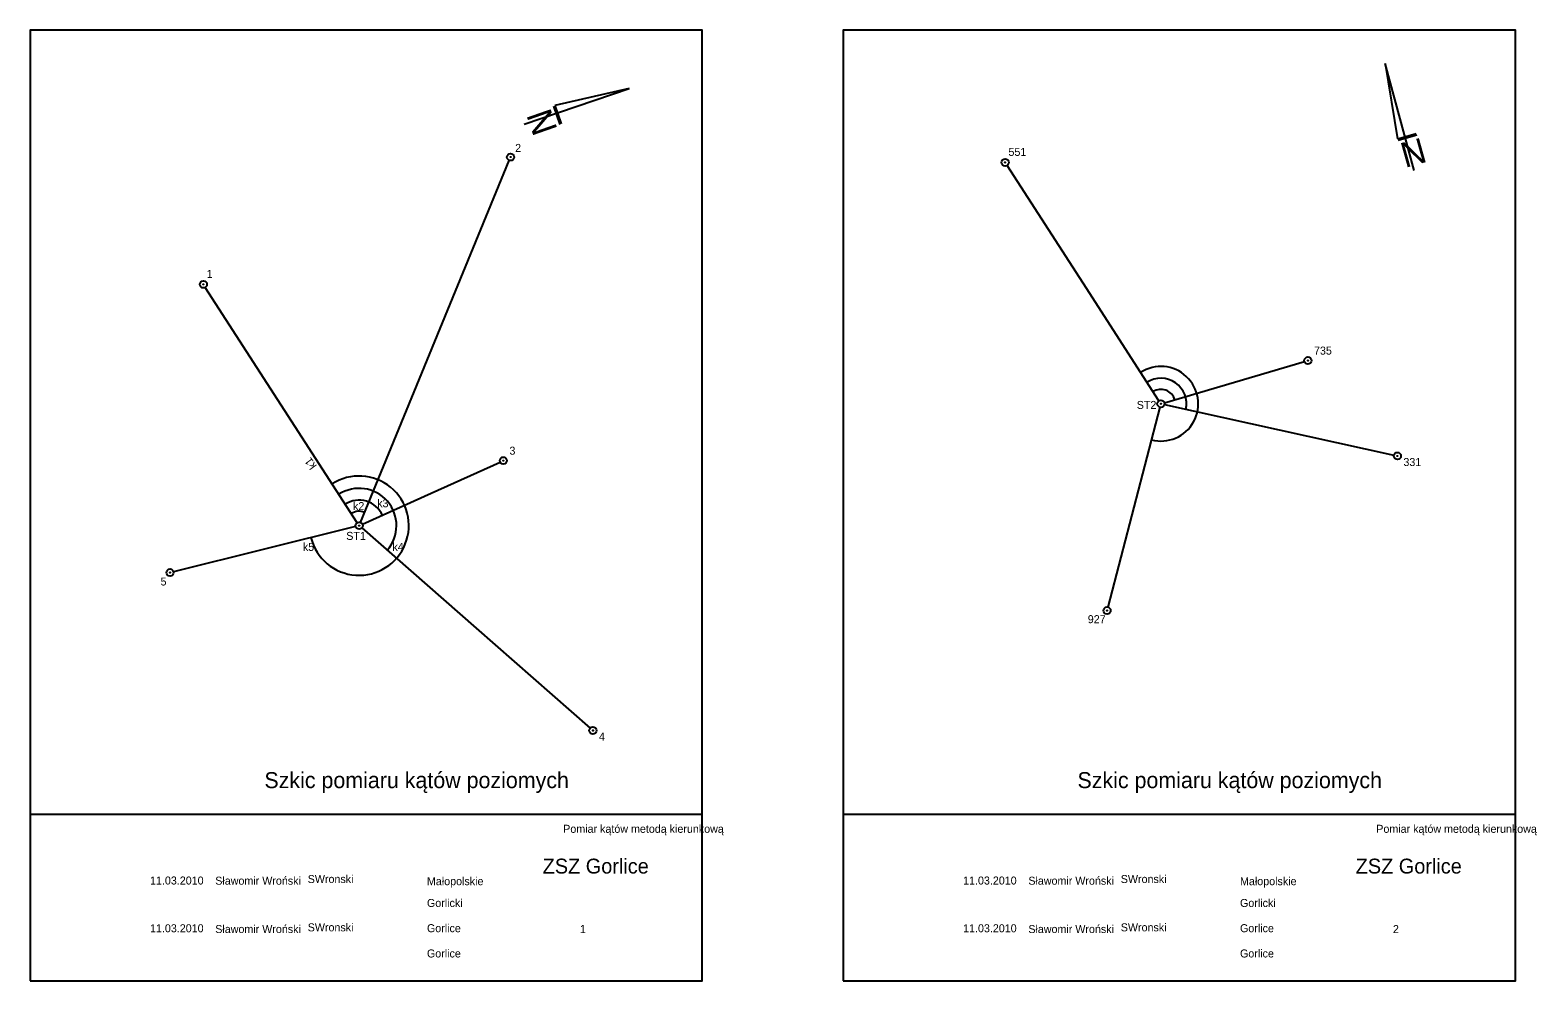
# Model space of a CAD drawing. Extents: x 4638556 to 4640059, y 5351940 to 5352237.
# Drawn here: x 4638555.6 to 4639026.3, y 5351939.6 to 5352236.6 of the extents above; entities that cross this region are included whole.
import ezdxf

# ---------------------------------------------------------------- set-up
doc = ezdxf.new("R2010")
doc.units = 0
doc.layers.add('Default', color=7, linetype='Continuous')

msp = doc.modelspace()

# ---------------------------------------------------------------- linework, layer by layer
at = {"layer": 'Default'}
for p, q in [((4638987.96, 5352192.76), (4638978.88, 5352226.2)), ((4638978.88, 5352226.2), (4638982.76, 5352202.68)), ((4638709.89, 5352207.23), (4638742.69, 5352218.39)), ((4638742.69, 5352218.39), (4638719.46, 5352213.04)), ((4638719.07, 5352212.85), (4638721.05, 5352207.17)), ((4638719.46, 5352213.04), (4638721.45, 5352207.36)), ((4638982.76, 5352202.68), (4638988.56, 5352204.31)), ((4638982.92, 5352202.28), (4638988.72, 5352203.9)), ((4638681.99, 5352139.38), (4638705.21, 5352195.92)), ((4638884.48, 5352157.59), (4638860.75, 5352194.34)), ((4638634, 5352119.5), (4638610.27, 5352156.25)), ((4638908.21, 5352120.83), (4638884.48, 5352157.59)), ((4638658.76, 5352082.84), (4638681.99, 5352139.38)), ((4638931.78, 5352126.64), (4638953.66, 5352133.07)), ((4638909.89, 5352120.21), (4638931.78, 5352126.64)), ((4638657.73, 5352082.75), (4638634, 5352119.5)), ((4638908.53, 5352118.81), (4638900.4, 5352087.59)), ((4638909.91, 5352119.65), (4638945.75, 5352111.74)), ((4638945.75, 5352111.74), (4638981.6, 5352103.83)), ((4638680.86, 5352091.97), (4638702.36, 5352101.67)), ((4638659.35, 5352082.27), (4638680.86, 5352091.97)), ((4638900.4, 5352087.59), (4638892.27, 5352056.37)), ((4638657.25, 5352081.54), (4638628.8, 5352074.49)), ((4638659.19, 5352081.09), (4638694.86, 5352049.82)), ((4638628.8, 5352074.49), (4638600.34, 5352067.44)), ((4638694.86, 5352049.82), (4638730.53, 5352018.56))]:
    msp.add_line(p, q, dxfattribs=at)
for points in [[(4638555.55, 5351939.61), (4638765.55, 5351939.61), (4638765.55, 5352236.61), (4638555.55, 5352236.61)], [(4638809.56, 5351939.61), (4639019.56, 5351939.61), (4639019.56, 5352236.61), (4638809.56, 5352236.61)], [(4638555.55, 5351939.61), (4638765.55, 5351939.61), (4638765.55, 5351991.61), (4638555.55, 5351991.61)], [(4638809.56, 5351939.61), (4639019.56, 5351939.61), (4639019.56, 5351991.61), (4638809.56, 5351991.61)]]:
    msp.add_lwpolyline(points, close=True, dxfattribs=at)
for centre, radius in [((4638705.64, 5352196.96), 1.12), ((4638705.64, 5352196.96), 0.0804), ((4638860.15, 5352195.28), 1.12), ((4638860.15, 5352195.28), 0.0804), ((4638609.67, 5352157.19), 1.12), ((4638609.67, 5352157.19), 0.0804), ((4638954.74, 5352133.39), 1.12), ((4638954.74, 5352133.39), 0.0804), ((4638908.81, 5352119.89), 1.12), ((4638908.81, 5352119.89), 0.0804), ((4638982.7, 5352103.59), 1.12), ((4638703.38, 5352102.13), 1.12), ((4638703.38, 5352102.13), 0.0804), ((4638982.7, 5352103.59), 0.0804), ((4638658.34, 5352081.81), 1.12), ((4638658.34, 5352081.81), 0.0804), ((4638599.25, 5352067.17), 1.12), ((4638599.25, 5352067.17), 0.0804), ((4638891.99, 5352055.29), 1.12), ((4638891.99, 5352055.29), 0.0804), ((4638731.37, 5352017.82), 1.12), ((4638731.37, 5352017.82), 0.0804)]:
    msp.add_circle(centre, radius, dxfattribs=at)
for centre, radius, start in [((4638908.81, 5352119.89), 11.66, 255.3991), ((4638908.81, 5352119.89), 7.98, 347.557), ((4638908.81, 5352119.89), 4.51, 16.3755), ((4638658.34, 5352081.81), 15.51, 193.9113), ((4638658.34, 5352081.81), 11.66, 318.8815), ((4638658.34, 5352081.81), 7.98, 24.287), ((4638658.34, 5352081.81), 4.51, 67.6678)]:
    msp.add_arc(centre, radius, start, 122.8465, dxfattribs=at)

# ---------------------------------------------------------------- texts
for s, height, rotation, p in [('N', 7.81, 289.2401, (4638710.5, 5352210.14)), ('N', 7.81, 15.6452, (4638985.09, 5352193.55)), ('k1', 2.5, 126.0823, (4638645.21, 5352100.52))]:
    msp.add_text(s, height=height, rotation=rotation, dxfattribs=at).set_placement(p)
for s, height, p in [('2', 2.5, (4638707.08, 5352198.56)), ('551', 2.5, (4638861.19, 5352197.32)), ('1', 2.5, (4638610.71, 5352159.23)), ('735', 2.5, (4638956.64, 5352135.25)), ('ST2', 2.5, (4638901.27, 5352118.28)), ('3', 2.5, (4638705.29, 5352103.98)), ('331', 2.5, (4638984.57, 5352100.44)), ('k3', 2.5, (4638663.98, 5352087.56)), ('k2', 2.5, (4638656.43, 5352086.67)), ('k5', 2.5, (4638640.75, 5352073.93)), ('ST1', 2.5, (4638654.31, 5352077.37)), ('k4', 2.5, (4638668.74, 5352073.93)), ('5', 2.5, (4638596.29, 5352063.12)), ('927', 2.5, (4638885.97, 5352051.35)), ('4', 2.5, (4638733.25, 5352014.67)), ('Szkic pomiaru kątów poziomych', 5, (4638628.74, 5351999.82)), ('Szkic pomiaru kątów poziomych', 5, (4638882.75, 5351999.82)), ('Pomiar kątów metodą kierunkową', 2.5, (4638722.09, 5351985.86)), ('Pomiar kątów metodą kierunkową', 2.5, (4638976.1, 5351985.86)), ('ZSZ Gorlice', 4.6473, (4638715.67, 5351973.14)), ('ZSZ Gorlice', 4.6473, (4638969.67, 5351973.14)), ('SWronski', 2.5, (4638642.27, 5351970.18)), ('SWronski', 2.5, (4638896.28, 5351970.18)), ('11.03.2010', 2.5, (4638593.01, 5351969.71)), ('Sławomir Wroński', 2.5, (4638613.39, 5351969.65)), ('Małopolskie', 2.5, (4638679.52, 5351969.5)), ('11.03.2010', 2.5, (4638847.02, 5351969.71)), ('Sławomir Wroński', 2.5, (4638867.4, 5351969.65)), ('Małopolskie', 2.5, (4638933.53, 5351969.5)), ('Gorlicki', 2.5, (4638679.52, 5351962.7)), ('Gorlicki', 2.5, (4638933.53, 5351962.7)), ('11.03.2010', 2.5, (4638593.01, 5351954.79)), ('Sławomir Wroński', 2.5, (4638613.39, 5351954.55)), ('SWronski', 2.5, (4638642.27, 5351955.08)), ('Gorlice', 2.5, (4638679.52, 5351954.81)), ('1', 2.5, (4638727.3, 5351954.55)), ('11.03.2010', 2.5, (4638847.02, 5351954.79)), ('Sławomir Wroński', 2.5, (4638867.4, 5351954.55)), ('SWronski', 2.5, (4638896.28, 5351955.08)), ('Gorlice', 2.5, (4638933.53, 5351954.81)), ('2', 2.5, (4638981.31, 5351954.55)), ('Gorlice', 2.5, (4638679.52, 5351946.92)), ('Gorlice', 2.5, (4638933.53, 5351946.92))]:
    msp.add_text(s, height=height, dxfattribs=at).set_placement(p)

doc.saveas('drawing.dxf')
